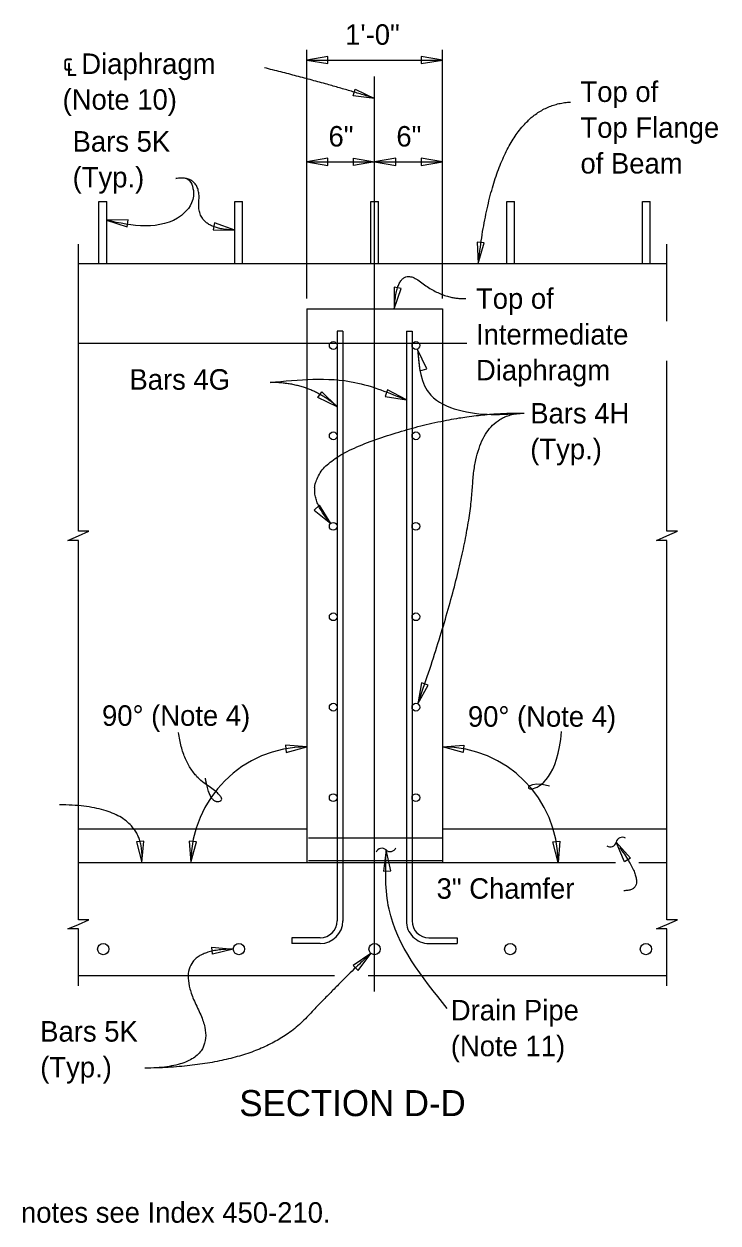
# Model space of a CAD drawing. Extents: x 0 to 54.1, y -6.1 to 22.7.
# Drawn here: x 10.59 to 15.71, y 4.9 to 13.74 of the extents above; entities that cross this region are included whole.
import ezdxf

# ---------------------------------------------------------------- set-up
doc = ezdxf.new("R2010")
doc.units = 0
for name, color, linetype in [('BeamConc', 7, 'Continuous'), ('BeamConc_h', 7, 'Continuous'), ('CL_Major', 7, 'Continuous'), ('Dimension', 7, 'Continuous'), ('Miscellaneous', 7, 'Continuous'), ('Rebar', 7, 'Continuous'), ('TextStructures', 7, 'Continuous')]:
    doc.layers.add(name, color=color, linetype=linetype)

msp = doc.modelspace()

# ---------------------------------------------------------------- linework, layer by layer
at = {"layer": 'BeamConc'}
for p, q in [((10.9942, 11.9734), (15.3312, 11.9734)), ((12.6766, 11.6401), (12.6766, 7.5567)), ((12.6766, 11.6401), (13.6766, 11.6401)), ((13.6766, 11.6401), (13.6766, 7.5567)), ((10.9942, 7.8067), (12.6766, 7.8067)), ((13.6766, 7.8067), (15.3312, 7.8067)), ((10.9942, 7.5567), (14.9535, 7.5567)), ((15.1234, 7.5567), (15.3312, 7.5567)), ((10.9942, 6.7234), (12.8809, 6.7234)), ((13.1283, 6.7234), (15.3312, 6.7234))]:
    msp.add_line(p, q, dxfattribs=at)
at = {"layer": 'BeamConc_h'}
msp.add_line((10.9942, 11.385), (13.8556, 11.385), dxfattribs=at)
at = {"layer": 'CL_Major'}
msp.add_line((13.1766, 6.6051), (13.1766, 13.3526), dxfattribs=at)
at = {"layer": 'Dimension'}
for p, q in [((12.6766, 11.7157), (12.6766, 13.549)), ((13.6766, 11.7157), (13.6766, 13.549)), ((12.6766, 13.4734), (13.6766, 13.4734)), ((12.6766, 12.7234), (13.6766, 12.7234))]:
    msp.add_line(p, q, dxfattribs=at)
for points in [[(12.6767, 13.4734), (12.8329, 13.447), (12.8329, 13.4999)], [(13.6766, 13.4734), (13.5204, 13.4999), (13.5204, 13.447)], [(13.1769, 13.1906), (13.0195, 13.2089), (13.0343, 13.2597)], [(12.6767, 12.7234), (12.8329, 12.697), (12.8329, 12.7499)], [(13.1766, 12.7234), (13.0204, 12.697), (13.0204, 12.7499)], [(13.1766, 12.7234), (13.3328, 12.697), (13.3328, 12.7499)], [(13.6766, 12.7234), (13.5204, 12.7499), (13.5204, 12.697)], [(11.2012, 12.2922), (11.352, 12.2437), (11.3596, 12.2961)], [(11.2012, 12.2922), (11.2017, 12.2921), (11.2017, 12.2923)], [(12.1456, 12.2204), (11.9963, 12.2733), (11.9872, 12.2211)], [(13.941, 11.9734), (13.9854, 12.1255), (13.9329, 12.1316)], [(13.3217, 11.6401), (13.3727, 11.7901), (13.3204, 11.7985)], [(13.4923, 11.3386), (13.5108, 11.1813), (13.5616, 11.1962)], [(12.9009, 10.9172), (12.7576, 10.9846), (12.7878, 11.0281)], [(13.4108, 10.9678), (13.2715, 11.0431), (13.2544, 10.993)], [(12.8554, 10.0578), (12.7698, 10.1911), (12.7307, 10.1554)], [(13.4961, 8.726), (13.5725, 8.8648), (13.5225, 8.8822)], [(12.6765, 8.4102), (12.5191, 8.4225), (12.5239, 8.3694)], [(13.6766, 8.4102), (13.834, 8.4225), (13.8291, 8.3694)], [(11.4607, 7.5569), (11.475, 7.7146), (11.4223, 7.7106)], [(11.823, 7.5567), (11.8638, 7.7093), (11.8107, 7.7141)], [(14.5301, 7.5567), (14.4893, 7.7093), (14.5425, 7.7141)], [(14.9568, 7.7072), (15.063, 7.5897), (15.0184, 7.5613)], [(13.2619, 7.6499), (13.243, 7.4927), (13.2959, 7.4952)], [(12.1354, 6.9181), (11.9813, 6.8813), (11.9778, 6.9341)], [(13.1497, 6.8876), (13.0184, 6.7989), (13.0549, 6.7606)]]:
    msp.add_lwpolyline(points, close=True, dxfattribs=at)
for points in [[(10.9942, 7.5567), (10.9942, 9.9323), (10.9167, 9.9323), (10.9942, 9.9661), (11.0717, 9.9998), (10.9942, 9.9998), (10.9942, 12.1152)], [(15.3312, 11.5493), (15.3312, 12.1152)], [(15.3312, 7.5567), (15.3312, 9.9323), (15.2537, 9.9323), (15.3312, 9.9661), (15.4087, 9.9998), (15.3312, 9.9998), (15.3312, 11.2563)], [(10.9942, 6.6478), (10.9942, 7.0677), (10.9167, 7.0677), (10.9942, 7.1014), (11.0717, 7.1352), (10.9942, 7.1352), (10.9942, 7.5567)], [(15.3312, 6.6478), (15.3312, 7.0677), (15.2537, 7.0677), (15.3312, 7.1014), (15.4087, 7.1352), (15.3312, 7.1352), (15.3312, 7.5567)]]:
    msp.add_lwpolyline(points, dxfattribs=at)
for centre, radius, start, end in [((12.6766, 7.5567), 0.8535, 90, 180), ((13.6766, 7.5567), 0.8535, 0, 90), ((14.9135, 7.7165), 0.0447, 236.58686, 348.31408), ((15.0011, 7.6984), 0.0447, 56.58686, 168.31408), ((13.2308, 7.6172), 0.0447, 46.94989, 158.67711), ((13.2918, 7.6826), 0.0447, 226.94989, 338.67711)]:
    msp.add_arc(centre, radius, start, end, dxfattribs=at)
for points, degree in [([(13.1766, 13.1912), (12.8105, 13.3052), (12.3651, 13.4162)], 2), ([(13.941, 11.9734), (14.071, 13.1376), (14.6202, 13.1633)], 2), ([(12.1456, 12.2204), (11.8648, 12.2241), (11.8987, 12.6252), (11.7113, 12.6002)], 2), ([(13.3217, 11.6401), (13.342, 11.9735), (13.6833, 11.7064), (13.8489, 11.7156)], 2), ([(12.9007, 10.9178), (12.704, 11.0961), (12.4075, 11.0972)], 2), ([(12.8554, 10.0578), (12.5179, 10.4284), (13.7351, 10.8788), (14.2795, 10.87)], 2), ([(13.4961, 8.726), (13.8686, 9.7948), (13.928, 10.8689), (14.2795, 10.87)], 2), ([(11.9274, 8.1802), (11.9584, 7.9938), (12.0992, 8.0215), (11.7685, 8.246), (11.7316, 8.5147)], 2), ([(14.4651, 8.1199), (14.3091, 8.1635), (14.254, 8.0215), (14.5305, 8.1938), (14.554, 8.5229)], 3), ([(11.4604, 7.5567), (11.501, 7.9821), (10.8545, 7.9821)], 2), ([(14.9817, 7.6682), (15.2169, 7.3492), (15.0127, 7.3492)], 2), ([(12.1354, 6.918), (11.6508, 6.9209), (12.0941, 6.0458), (11.4842, 6.0409)], 2), ([(13.1497, 6.8875), (13.0024, 6.7574), (12.3267, 6.0508), (11.4842, 6.0409)], 2)]:
    msp.add_open_spline(points, degree=degree, dxfattribs=at)
for points in [[(11.7113, 12.6002), (11.7917, 12.6002), (11.8421, 12.4941), (11.7531, 12.3278), (11.489, 12.2507), (11.2012, 12.2922)], [(13.4923, 11.3387), (13.5905, 11.0034), (13.7925, 10.8942), (14.2795, 10.87)], [(12.4075, 11.0972), (13.0302, 11.0972), (13.4108, 10.9677)], [(13.7125, 6.4815), (13.283, 7.2136), (13.2619, 7.65)]]:
    msp.add_spline(points, degree=3, dxfattribs=at)
at = {"layer": 'Miscellaneous'}
for p, q in [((12.6895, 7.7404), (13.6766, 7.7404)), ((12.6895, 7.5727), (13.6766, 7.5727))]:
    msp.add_line(p, q, dxfattribs=at)
at = {"layer": 'Rebar'}
for p, q in [((11.1454, 11.9734), (11.1454, 12.4317)), ((11.1454, 12.4317), (11.2027, 12.4317)), ((11.2027, 11.9734), (11.2027, 12.4317)), ((12.1456, 11.9734), (12.1456, 12.4317)), ((12.1456, 12.4317), (12.203, 12.4317)), ((12.203, 11.9734), (12.203, 12.4317)), ((13.1479, 11.9734), (13.1479, 12.4317)), ((13.1479, 12.4317), (13.2053, 12.4317)), ((13.2053, 11.9734), (13.2053, 12.4317)), ((14.1505, 11.9734), (14.1505, 12.4317)), ((14.1505, 12.4317), (14.2079, 12.4317)), ((14.2079, 11.9734), (14.2079, 12.4317)), ((15.1505, 11.9734), (15.1505, 12.4317)), ((15.1505, 12.4317), (15.2079, 12.4317)), ((15.2079, 11.9734), (15.2079, 12.4317)), ((12.9007, 11.4734), (12.9007, 7.1267)), ((12.9423, 11.4734), (12.9007, 11.4734)), ((12.9423, 11.4734), (12.9423, 7.1245)), ((13.4109, 11.4734), (13.4109, 7.1245)), ((13.4109, 11.4734), (13.4526, 11.4734)), ((13.4526, 11.4734), (13.4526, 7.1267)), ((12.5673, 7.0017), (12.5673, 6.9601)), ((12.7757, 7.0017), (12.5673, 7.0017)), ((13.5776, 7.0017), (13.7859, 7.0017)), ((13.7859, 7.0017), (13.7859, 6.9601)), ((12.7756, 6.96), (12.5673, 6.96)), ((13.5776, 6.96), (13.7859, 6.96))]:
    msp.add_line(p, q, dxfattribs=at)
for centre, radius in [((12.872, 11.3692), 0.0287), ((13.4813, 11.3692), 0.0287), ((12.872, 10.7025), 0.0287), ((13.4813, 10.7025), 0.0287), ((12.872, 10.0358), 0.0287), ((13.4813, 10.0358), 0.0287), ((12.872, 9.3691), 0.0287), ((13.4813, 9.3691), 0.0287), ((12.872, 8.7024), 0.0287), ((13.4813, 8.7024), 0.0287), ((12.872, 8.0357), 0.0287), ((13.4813, 8.0357), 0.0287), ((11.1766, 6.9188), 0.0413), ((12.1766, 6.9188), 0.0413), ((13.1766, 6.9188), 0.0413), ((14.1766, 6.9188), 0.0413), ((15.1766, 6.9188), 0.0413)]:
    msp.add_circle(centre, radius, dxfattribs=at)
for centre, radius, start, end in [((12.7757, 7.1267), 0.125, 270, 0), ((12.7757, 7.1267), 0.1667, 270, 360), ((13.5776, 7.1267), 0.1667, 179.24004, 270), ((13.5776, 7.1267), 0.125, 180, 270)]:
    msp.add_arc(centre, radius, start, end, dxfattribs=at)

# ---------------------------------------------------------------- texts
at = {"layer": 'Dimension'}
for s, p in [('Top of', (14.6942, 13.1646)), ('Top Flange', (14.6942, 12.9006)), ('Bars 5K', (10.951, 12.798)), ('of Beam', (14.6942, 12.6366)), ('(Typ.)', (10.951, 12.534)), ('Top of', (13.9241, 11.6396)), ('Intermediate', (13.9241, 11.3756)), ('Diaphragm', (13.9241, 11.1116)), ('Bars 4H', (14.3241, 10.794)), ('(Typ.)', (14.3241, 10.53)), ('Drain Pipe', (13.7385, 6.3932)), ('Bars 5K', (10.7123, 6.2368)), ('(Note 11)', (13.7385, 6.1292)), ('(Typ.)', (10.7123, 5.9728))]:
    msp.add_text(s, height=0.1512, dxfattribs=at).set_placement(p)
at = {"layer": 'TextStructures'}
for s, height, p in [('1\'-0"', 0.1512, (12.9596, 13.5858)), ('℄ Diaphragm', 0.1512, (10.877, 13.3705)), ('(Note 10)', 0.1512, (10.877, 13.1074)), ('6"', 0.1512, (12.8371, 12.8358)), ('6"', 0.1512, (13.3373, 12.8358)), ('Bars 4G', 0.1512, (11.3698, 11.043)), ('90° (Note 4)', 0.1512, (11.1679, 8.565)), ('90° (Note 4)', 0.1512, (13.8647, 8.5583)), ('3" Chamfer', 0.1512, (13.6339, 7.2901)), ('SECTION D-D', 0.192, (12.1797, 5.6874)), ('For referenced notes see Index 450-210.', 0.1512, (9.1883, 4.9016))]:
    msp.add_text(s, height=height, dxfattribs=at).set_placement(p)

doc.saveas('drawing.dxf')
